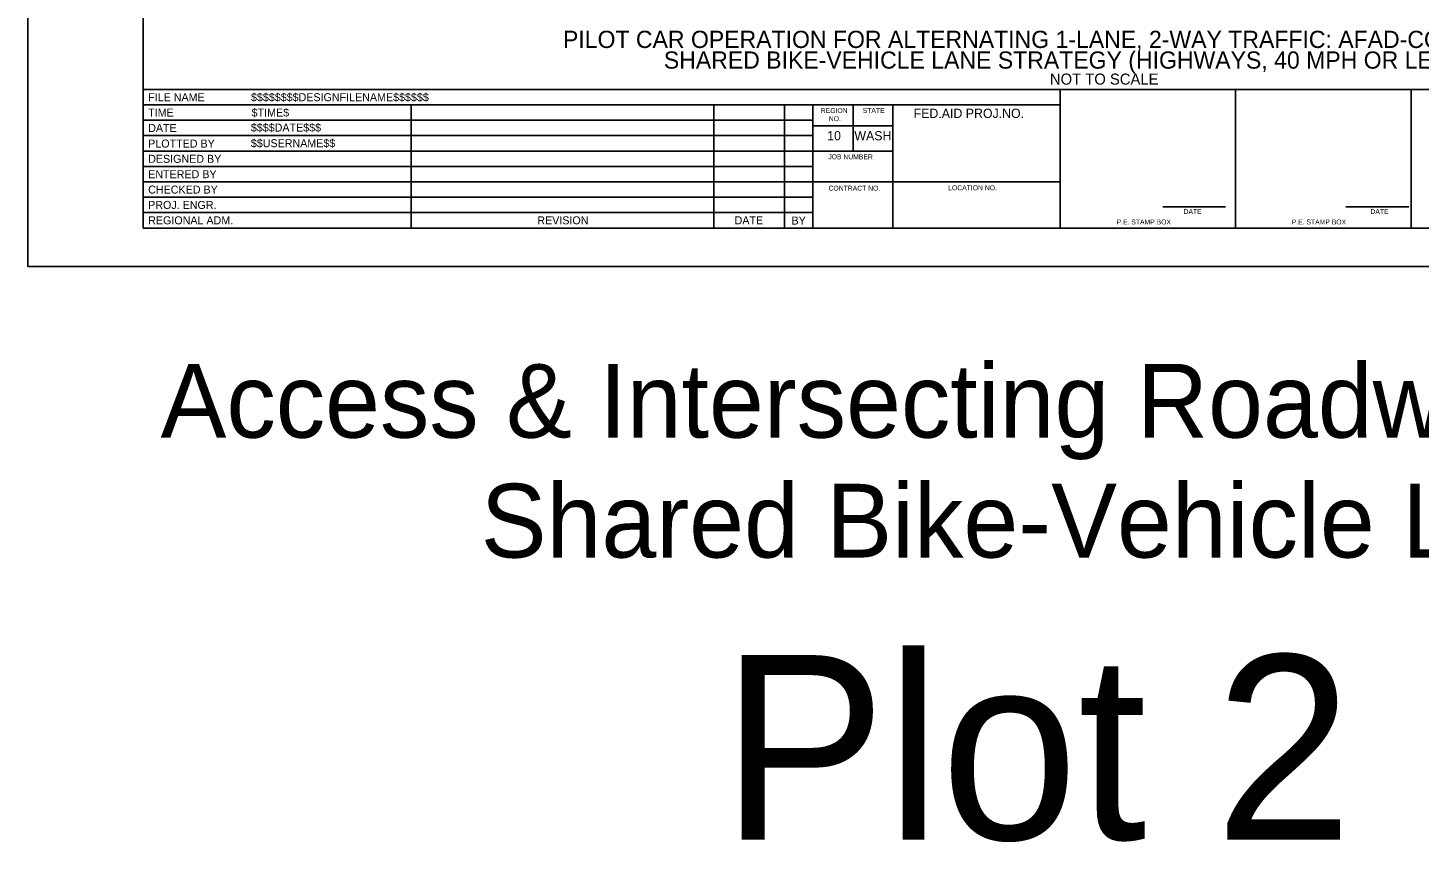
# Model space of a CAD drawing. Extents: x 99999.1 to 100095.7, y 99995 to 100010.7.
# Drawn here: x 100019.06 to 100030.38, y 99995.01 to 100001.63 of the extents above; entities that cross this region are included whole.
import ezdxf

# ---------------------------------------------------------------- set-up
doc = ezdxf.new("R2010")
doc.units = 0
for name, color, linetype in [('SH_DE_DetailHeading1Text', 7, 'Continuous'), ('SH_GI_PlotLimits', 7, 'Continuous'), ('SH_GI_SheetBorder', 7, 'Continuous'), ('SH_GI_SheetLocationText', 7, 'Continuous'), ('SH_GI_SheetTextInCells', 7, 'Continuous'), ('SH_GI_TitleBlockText', 7, 'Continuous')]:
    doc.layers.add(name, color=color, linetype=linetype)

msp = doc.modelspace()

# ---------------------------------------------------------------- linework, layer by layer
at = {"layer": 'SH_GI_PlotLimits'}
msp.add_lwpolyline([(100019.062, 99999.687), (100036.062, 99999.687), (100036.062, 100010.687), (100019.062, 100010.687)], close=True, dxfattribs=at)
at = {"layer": 'SH_GI_SheetBorder'}
for p, q in [((100020, 100010.375), (100020, 100000)), ((100020, 100001.126), (100035.75, 100001.126)), ((100027.457, 100000), (100027.457, 100001.126)), ((100028.883, 100000), (100028.883, 100001.126)), ((100030.309, 100001.126), (100030.309, 100000)), ((100020, 100001.001), (100027.457, 100001.001)), ((100022.179, 100001.001), (100022.179, 100000)), ((100024.641, 100001.001), (100024.641, 100000)), ((100025.216, 100001.001), (100025.216, 100000)), ((100025.445, 100001.001), (100025.445, 100000)), ((100025.772, 100000.625), (100025.772, 100001.001)), ((100026.096, 100000), (100026.096, 100001.001)), ((100020, 100000.876), (100022.182, 100000.876)), ((100022.182, 100000.876), (100025.447, 100000.876)), ((100026.096, 100000.831), (100025.447, 100000.831)), ((100020, 100000.751), (100022.182, 100000.751)), ((100022.182, 100000.751), (100025.447, 100000.751)), ((100020, 100000.625), (100025.447, 100000.625)), ((100026.096, 100000.625), (100025.447, 100000.625)), ((100020, 100000.5), (100025.447, 100000.5)), ((100020, 100000.375), (100025.447, 100000.375)), ((100027.457, 100000.375), (100025.447, 100000.375)), ((100020, 100000.25), (100025.447, 100000.25)), ((100020, 100000.125), (100025.447, 100000.125)), ((100028.29, 100000.173), (100028.802, 100000.173)), ((100029.78, 100000.173), (100030.291, 100000.173)), ((100020, 100000), (100035.75, 100000))]:
    msp.add_line(p, q, dxfattribs=at)

# ---------------------------------------------------------------- texts
at = {"layer": 'SH_DE_DetailHeading1Text'}
for s, height, p in [('PILOT CAR OPERATION FOR ALTERNATING 1-LANE, 2-WAY TRAFFIC: AFAD-CONTROLLED', 0.14, (100023.414, 100001.464)), ('SHARED BIKE-VEHICLE LANE STRATEGY (HIGHWAYS, 40 MPH OR LESS)', 0.14, (100024.234, 100001.296)), ('NOT TO SCALE', 0.09, (100027.373, 100001.166))]:
    msp.add_text(s, height=height, rotation=360, dxfattribs=at).set_placement(p)
at = {"layer": 'SH_GI_SheetLocationText'}
for s, height, p in [('Access & Intersecting Roadway Details', 0.6, (100020.142, 99998.295)), ('Shared Bike-Vehicle Lane', 0.6, (100022.745, 99997.32)), ('Plot 2', 1.5, (100024.702, 99995.027))]:
    msp.add_text(s, height=height, dxfattribs=at).set_placement(p)
at = {"layer": 'SH_GI_SheetTextInCells'}
for s, height, p in [('FILE NAME', 0.0651, (100020.041, 100001.031)), ('TIME', 0.0651, (100020.041, 100000.906)), ('REGION', 0.04, (100025.51, 100000.935)), ('NO.', 0.04, (100025.575, 100000.869)), ('STATE', 0.04, (100025.851, 100000.936)), ('FED.AID PROJ.NO.', 0.07506, (100026.265, 100000.895)), ('DATE', 0.0651, (100020.041, 100000.781)), ('10', 0.0751, (100025.562, 100000.713)), ('WASH', 0.0751, (100025.783, 100000.713)), ('PLOTTED BY', 0.0651, (100020.041, 100000.654)), ('DESIGNED BY', 0.06505, (100020.041, 100000.53)), ('JOB NUMBER', 0.04, (100025.571, 100000.559)), ('ENTERED BY', 0.0651, (100020.041, 100000.405)), ('CHECKED BY', 0.0651, (100020.041, 100000.28)), ('CONTRACT NO.', 0.04003, (100025.573, 100000.304)), ('LOCATION NO.', 0.04003, (100026.546, 100000.307)), ('PROJ. ENGR.', 0.06505, (100020.041, 100000.155)), ('REGIONAL ADM.', 0.06505, (100020.041, 100000.03)), ('REVISION', 0.0651, (100023.205, 100000.03)), ('DATE', 0.04, (100028.46, 100000.114)), ('DATE', 0.04, (100029.979, 100000.114)), ('DATE', 0.0651, (100024.809, 100000.03)), ('BY', 0.0651, (100025.272, 100000.028)), ('P.E. STAMP BOX', 0.04003, (100027.915, 100000.029)), ('P.E. STAMP BOX', 0.04003, (100029.339, 100000.029))]:
    msp.add_text(s, height=height, dxfattribs=at).set_placement(p)
at = {"layer": 'SH_GI_TitleBlockText'}
for s, height, p in [('$$$$$$$$DESIGNFILENAME$$$$$$', 0.06505, (100020.877, 100001.031)), ('$TIME$', 0.0651, (100020.882, 100000.906)), ('$$$$DATE$$$', 0.06505, (100020.876, 100000.784)), ('$$USERNAME$$', 0.06505, (100020.876, 100000.657))]:
    msp.add_text(s, height=height, dxfattribs=at).set_placement(p)

doc.saveas('drawing.dxf')
